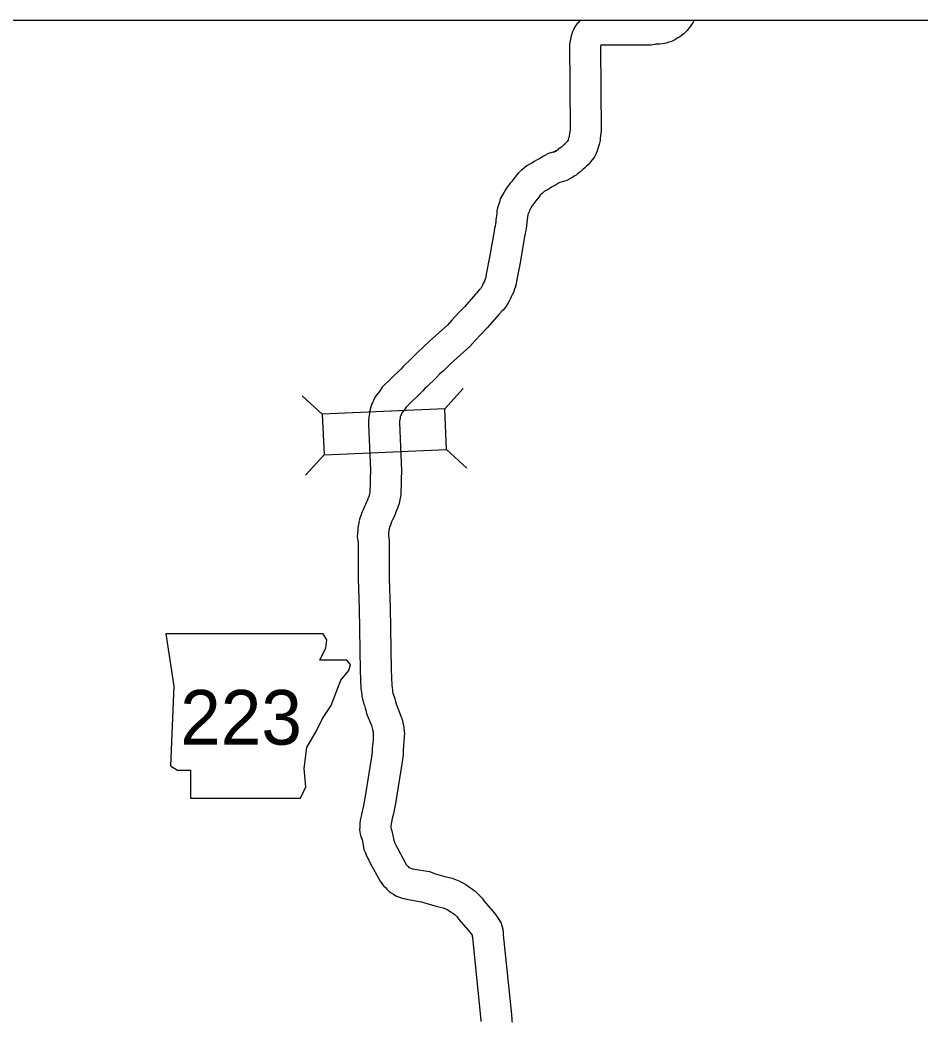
# Model space of a CAD drawing. Extents: x 1377389 to 1380723, y 1168351 to 1170484.
# Drawn here: x 1377955.3 to 1378042.4, y 1170291.8 to 1170388.8 of the extents above; entities that cross this region are included whole.
import ezdxf

# ---------------------------------------------------------------- set-up
doc = ezdxf.new("R2010")
doc.units = 0
doc.layers.add('B_Fill', color=7, linetype='Continuous')
doc.layers.add('B_Text', color=7, linetype='Continuous')

msp = doc.modelspace()

# ---------------------------------------------------------------- linework, layer by layer
at = {"layer": 'B_Fill'}
for p, q in [((1377996.362, 1170351.155), (1377998.146, 1170353.101)), ((1377984.494, 1170350.635), (1377982.547, 1170352.418)), ((1377996.536, 1170347.199), (1377998.482, 1170345.415)), ((1377984.667, 1170346.679), (1377982.884, 1170344.732))]:
    msp.add_line(p, q, dxfattribs=at)
for points in [[(1378009.472, 1170388.771), (1378009.248, 1170388.506), (1378009.182, 1170388.423), (1378008.939, 1170388.113), (1378008.81, 1170387.838), (1378008.716, 1170387.638), (1378008.644, 1170387.426), (1378008.552, 1170387.127), (1378008.547, 1170387.085), (1378008.48, 1170386.767), (1378008.426, 1170386.456), (1378008.501, 1170378.239), (1378008.486, 1170378.145), (1378008.414, 1170377.836), (1378008.377, 1170377.497), (1378008.377, 1170377.465), (1378008.341, 1170377.337), (1378008.311, 1170377.194), (1378008.293, 1170377.137), (1378008.198, 1170377.031), (1378008.039, 1170376.851), (1378007.989, 1170376.787), (1378007.926, 1170376.726), (1378007.859, 1170376.656), (1378007.744, 1170376.558), (1378007.648, 1170376.471), (1378007.338, 1170376.263), (1378007.261, 1170376.189), (1378007.147, 1170376.109), (1378006.876, 1170375.961)], [(1378020.475, 1170388.771), (1378020.38, 1170388.563), (1378020.119, 1170388.133), (1378019.805, 1170387.759), (1378019.503, 1170387.424), (1378019.089, 1170387.14), (1378018.857, 1170387.017), (1378018.67, 1170386.903), (1378018.286, 1170386.699), (1378018.023, 1170386.627), (1378017.777, 1170386.538), (1378017.38, 1170386.469), (1378017.151, 1170386.451), (1378017.032, 1170386.439), (1378016.79, 1170386.42), (1378016.685, 1170386.417), (1378016.674, 1170386.416), (1378016.31, 1170386.335), (1378011.508, 1170386.353), (1378011.468, 1170386.359), (1378011.443, 1170386.278), (1378011.428, 1170386.206), (1378011.504, 1170378.012), (1378011.431, 1170377.563), (1378011.381, 1170377.348), (1378011.386, 1170377.1), (1378011.282, 1170376.712), (1378011.256, 1170376.62), (1378011.214, 1170376.421), (1378011.111, 1170376.102), (1378011.021, 1170375.871), (1378010.856, 1170375.547), (1378010.612, 1170375.231), (1378010.443, 1170375.041), (1378010.349, 1170374.934), (1378010.224, 1170374.774), (1378010.053, 1170374.609), (1378009.924, 1170374.474), (1378009.726, 1170374.305), (1378009.405, 1170374.014), (1378009.216, 1170373.907), (1378009.074, 1170373.77), (1378008.865, 1170373.649), (1378008.732, 1170373.556), (1378008.17, 1170373.25)], [(1378007.172, 1170376.083), (1378006.39, 1170375.854), (1378005.894, 1170375.601), (1378005.547, 1170375.385), (1378005.241, 1170375.215), (1378004.992, 1170375.08), (1378004.764, 1170374.928), (1378004.594, 1170374.828), (1378004.3, 1170374.661), (1378004.063, 1170374.474), (1378003.764, 1170374.238), (1378003.501, 1170373.972), (1378003.298, 1170373.755), (1378003.094, 1170373.485), (1378002.969, 1170373.324), (1378002.834, 1170373.16), (1378002.68, 1170372.97), (1378002.534, 1170372.77), (1378002.372, 1170372.558), (1378002.18, 1170372.256), (1378002.106, 1170372.117), (1378001.947, 1170371.869), (1378001.712, 1170371.456), (1378001.642, 1170371.143), (1378001.604, 1170371.056), (1378001.442, 1170370.609), (1378001.401, 1170370.297), (1378001.378, 1170370.042), (1378001.35, 1170369.801), (1378001.33, 1170369.648), (1378001.296, 1170369.428), (1378001.283, 1170369.193), (1378001.266, 1170369.075), (1378001.217, 1170368.826), (1378001.181, 1170368.613), (1378001.132, 1170368.335), (1378000.696, 1170365.815), (1378000.373, 1170364.162), (1378000.336, 1170363.887), (1378000.255, 1170363.709), (1378000.201, 1170363.517), (1378000.195, 1170363.503), (1378000.082, 1170363.294), (1378000.008, 1170363.121), (1377999.94, 1170362.993), (1377999.882, 1170362.89), (1377999.8, 1170362.76), (1377999.767, 1170362.713), (1377999.699, 1170362.651), (1377999.547, 1170362.488), (1377999.422, 1170362.343), (1377999.339, 1170362.255), (1377999.131, 1170362.01), (1377998.265, 1170361.025), (1377997.727, 1170360.469), (1377997.023, 1170359.738), (1377996.614, 1170359.254), (1377994.914, 1170357.726), (1377994.197, 1170357.043), (1377993.764, 1170356.657), (1377993.387, 1170356.265), (1377993.139, 1170356.009), (1377992.876, 1170355.768), (1377992.599, 1170355.492), (1377992.326, 1170355.245), (1377992.091, 1170354.994), (1377990.3, 1170353.231), (1377990.027, 1170352.829), (1377989.821, 1170352.579), (1377989.652, 1170352.347), (1377989.497, 1170352.035), (1377989.464, 1170351.946), (1377989.432, 1170351.889), (1377989.361, 1170351.735), (1377989.277, 1170351.551), (1377989.12, 1170351.106), (1377989.064, 1170350.689), (1377989.006, 1170350.38), (1377988.971, 1170349.955), (1377988.981, 1170349.66), (1377989.178, 1170345.163), (1377989.135, 1170344.423), (1377989.135, 1170344.13), (1377989.123, 1170343.908), (1377989.119, 1170343.681), (1377989.11, 1170343.375), (1377989.104, 1170343.103), (1377989.065, 1170342.869), (1377989.047, 1170342.768), (1377989.004, 1170342.648), (1377988.906, 1170342.425), (1377988.839, 1170342.246), (1377988.787, 1170342.122), (1377988.693, 1170341.901), (1377988.586, 1170341.687), (1377988.448, 1170341.374), (1377988.338, 1170341.1), (1377988.25, 1170340.882), (1377988.145, 1170340.575), (1377988.085, 1170340.347)], [(1378008.17, 1170373.25), (1378007.504, 1170373.054), (1378007.37, 1170372.986), (1378007.069, 1170372.799), (1378006.686, 1170372.586), (1378006.542, 1170372.508), (1378006.358, 1170372.385), (1378006.095, 1170372.23), (1378005.976, 1170372.163), (1378005.921, 1170372.119), (1378005.77, 1170372), (1378005.664, 1170371.893), (1378005.597, 1170371.82), (1378005.474, 1170371.659), (1378005.311, 1170371.448), (1378005.157, 1170371.262), (1378005.061, 1170371.144), (1378004.938, 1170370.974), (1378004.831, 1170370.835), (1378004.776, 1170370.748), (1378004.699, 1170370.602), (1378004.539, 1170370.354), (1378004.507, 1170370.211), (1378004.395, 1170369.952), (1378004.377, 1170369.903), (1378004.362, 1170369.734), (1378004.327, 1170369.432), (1378004.299, 1170369.222), (1378004.284, 1170369.119), (1378004.271, 1170368.892), (1378004.223, 1170368.567), (1378004.169, 1170368.292), (1378004.138, 1170368.102), (1378004.086, 1170367.814), (1378003.646, 1170365.272), (1378003.335, 1170363.676), (1378003.279, 1170363.256), (1378003.174, 1170362.878), (1378003.08, 1170362.673), (1378003.026, 1170362.481), (1378002.883, 1170362.168), (1378002.787, 1170361.99), (1378002.713, 1170361.817), (1378002.573, 1170361.557), (1378002.461, 1170361.354), (1378002.296, 1170361.095), (1378002.041, 1170360.731), (1378001.817, 1170360.523), (1378001.776, 1170360.479), (1378001.65, 1170360.335), (1378001.578, 1170360.258), (1378001.401, 1170360.048), (1378000.47, 1170358.99), (1377999.885, 1170358.385), (1377999.252, 1170357.728), (1377998.774, 1170357.161), (1377996.952, 1170355.524), (1377996.231, 1170354.837), (1377995.846, 1170354.494), (1377995.545, 1170354.181), (1377995.231, 1170353.858), (1377994.949, 1170353.599), (1377994.664, 1170353.315), (1377994.431, 1170353.104), (1377994.24, 1170352.9), (1377992.616, 1170351.302), (1377992.43, 1170351.027), (1377992.234, 1170350.79), (1377992.192, 1170350.68), (1377992.11, 1170350.533), (1377992.088, 1170350.483), (1377992.06, 1170350.423), (1377992.052, 1170350.401), (1377992.027, 1170350.214), (1377991.983, 1170349.979), (1377991.975, 1170349.881), (1377991.979, 1170349.775), (1377992.182, 1170345.142), (1377992.135, 1170344.334), (1377992.135, 1170344.046), (1377992.122, 1170343.806), (1377992.119, 1170343.612), (1377992.109, 1170343.296), (1377992.099, 1170342.825), (1377992.021, 1170342.353), (1377991.954, 1170341.991), (1377991.795, 1170341.543), (1377991.688, 1170341.297), (1377991.626, 1170341.131), (1377991.548, 1170340.95), (1377991.418, 1170340.642), (1377991.301, 1170340.408), (1377991.214, 1170340.212), (1377991.121, 1170339.978), (1377991.061, 1170339.83), (1377991.02, 1170339.711), (1377990.99, 1170339.596)], [(1377988.076, 1170340.31), (1377987.99, 1170339.937), (1377987.954, 1170339.667), (1377987.927, 1170339.415), (1377987.904, 1170339.125), (1377987.872, 1170338.747), (1377987.951, 1170338.354), (1377987.96, 1170338.278), (1377987.98, 1170334.677), (1377988.074, 1170331.826), (1377988.161, 1170325.814), (1377988.239, 1170324.094), (1377988.288, 1170323.725), (1377988.315, 1170323.528), (1377988.341, 1170323.348), (1377988.383, 1170323.049), (1377988.478, 1170322.73), (1377988.534, 1170322.559), (1377988.572, 1170322.433), (1377988.647, 1170322.179), (1377988.714, 1170321.982), (1377988.793, 1170321.668), (1377989.258, 1170320.495), (1377989.336, 1170320.248), (1377989.361, 1170320.113), (1377989.411, 1170319.892), (1377989.428, 1170319.805), (1377989.435, 1170319.731), (1377989.442, 1170319.646), (1377989.441, 1170319.617), (1377989.437, 1170319.476), (1377989.418, 1170319.275), (1377989.41, 1170319.16), (1377989.382, 1170318.801), (1377989.344, 1170318.273), (1377989.339, 1170317.937), (1377989.256, 1170317.456), (1377988.628, 1170313.477), (1377988.494, 1170312.77), (1377988.419, 1170312.461), (1377988.349, 1170312.201), (1377988.253, 1170311.725), (1377988.179, 1170311.346), (1377988.124, 1170311.013), (1377988.119, 1170310.698), (1377988.112, 1170310.409), (1377988.167, 1170310.023), (1377988.245, 1170309.719), (1377988.325, 1170309.549), (1377988.34, 1170309.499), (1377988.345, 1170309.487), (1377988.534, 1170308.497), (1377988.671, 1170308.185), (1377988.748, 1170307.977), (1377988.9, 1170307.629), (1377989.011, 1170307.458), (1377989.115, 1170307.242), (1377990.102, 1170305.429), (1377990.429, 1170304.996), (1377990.574, 1170304.849), (1377990.734, 1170304.646), (1377990.972, 1170304.447), (1377991.168, 1170304.298), (1377991.384, 1170304.164), (1377991.617, 1170304.019), (1377991.87, 1170303.931), (1377991.981, 1170303.886), (1377992.238, 1170303.804), (1377992.427, 1170303.753), (1377992.647, 1170303.702), (1377994.117, 1170303.447), (1377994.535, 1170303.3), (1377995.608, 1170302.988), (1377996.195, 1170302.855), (1377996.498, 1170302.735), (1377996.531, 1170302.719), (1377996.647, 1170302.647), (1377996.795, 1170302.563), (1377996.918, 1170302.477), (1377997.127, 1170302.339), (1377997.229, 1170302.276), (1377997.264, 1170302.249), (1377997.35, 1170302.175), (1377997.428, 1170302.108), (1377997.513, 1170302.024), (1377997.562, 1170301.968), (1377997.715, 1170301.731), (1377998.657, 1170300.644), (1377998.895, 1170300.342), (1377999.006, 1170300.199), (1377999.017, 1170300.1), (1377999.032, 1170299.941), (1377999.82, 1170292.313), (1377999.831, 1170291.965), (1377999.835, 1170291.845)], [(1377990.999, 1170339.633), (1377990.945, 1170339.399), (1377990.933, 1170339.306), (1377990.914, 1170339.136), (1377990.897, 1170338.92), (1377990.914, 1170338.834), (1377990.959, 1170338.471), (1377990.98, 1170334.734), (1377991.073, 1170331.897), (1377991.16, 1170325.903), (1377991.23, 1170324.36), (1377991.261, 1170324.129), (1377991.286, 1170323.948), (1377991.312, 1170323.768), (1377991.323, 1170323.688), (1377991.34, 1170323.629), (1377991.395, 1170323.463), (1377991.447, 1170323.292), (1377991.507, 1170323.089), (1377991.595, 1170322.829), (1377991.655, 1170322.587), (1377992.085, 1170321.503), (1377992.253, 1170320.976), (1377992.301, 1170320.713), (1377992.346, 1170320.516), (1377992.4, 1170320.244), (1377992.424, 1170319.998), (1377992.45, 1170319.684), (1377992.439, 1170319.491), (1377992.433, 1170319.292), (1377992.408, 1170319.03), (1377992.402, 1170318.944), (1377992.374, 1170318.579), (1377992.343, 1170318.142), (1377992.335, 1170317.656), (1377992.216, 1170316.967), (1377991.584, 1170312.964), (1377991.428, 1170312.137), (1377991.326, 1170311.718), (1377991.271, 1170311.513), (1377991.195, 1170311.141), (1377991.132, 1170310.814), (1377991.12, 1170310.744), (1377991.119, 1170310.669), (1377991.183, 1170310.462), (1377991.244, 1170310.295), (1377991.417, 1170309.393), (1377991.454, 1170309.309), (1377991.531, 1170309.101), (1377991.552, 1170309.054), (1377991.631, 1170308.93), (1377991.785, 1170308.614), (1377992.631, 1170307.058), (1377992.703, 1170306.963), (1377992.827, 1170306.838), (1377992.887, 1170306.761), (1377992.913, 1170306.745), (1377992.999, 1170306.71), (1377993.085, 1170306.683), (1377993.16, 1170306.663), (1377993.243, 1170306.643), (1377994.875, 1170306.36), (1377995.451, 1170306.158), (1377996.36, 1170305.894), (1377997.085, 1170305.729), (1377997.715, 1170305.479), (1377997.988, 1170305.345), (1377998.179, 1170305.227), (1377998.399, 1170305.102), (1377998.603, 1170304.959), (1377998.743, 1170304.867), (1377998.947, 1170304.74), (1377999.159, 1170304.575), (1377999.3, 1170304.455), (1377999.469, 1170304.31), (1377999.695, 1170304.084), (1377999.958, 1170303.789), (1378000.121, 1170303.535), (1378000.971, 1170302.555), (1378001.255, 1170302.193), (1378001.489, 1170301.894), (1378001.601, 1170301.728), (1378001.813, 1170301.358), (1378001.846, 1170301.231), (1378001.982, 1170300.789), (1378001.992, 1170300.492), (1378002.002, 1170300.398), (1378002.017, 1170300.238), (1378002.815, 1170292.517), (1378002.83, 1170292.064), (1378002.834, 1170291.944)], [(1378002.829, 1170292.018), (1378002.842, 1170291.872), (1378002.871, 1170291.827), (1378002.899, 1170291.779)]]:
    msp.add_lwpolyline(points, dxfattribs=at)
for points in [[(1377996.362, 1170351.155), (1377984.494, 1170350.635), (1377984.667, 1170346.679), (1377996.536, 1170347.199)], [(1377969.375, 1170329.373), (1377970.137, 1170324.298), (1377969.798, 1170316.6), (1377970.475, 1170316.177), (1377971.744, 1170316.177), (1377971.744, 1170313.47), (1377982.402, 1170313.47), (1377982.91, 1170314.57), (1377982.741, 1170316.346), (1377982.994, 1170318.376), (1377983.925, 1170319.984), (1377984.517, 1170321.168), (1377985.363, 1170322.437), (1377985.87, 1170323.79), (1377986.293, 1170324.89), (1377987.055, 1170325.82), (1377987.224, 1170326.412), (1377986.885, 1170326.835), (1377984.263, 1170326.835), (1377984.855, 1170328.02), (1377984.94, 1170328.781), (1377984.589, 1170329.366)]]:
    msp.add_lwpolyline(points, close=True, dxfattribs=at)
at = {"layer": 'B_Text'}
msp.add_lwpolyline([(1377549.76, 1170388.771), (1378279.156, 1170388.771), (1378279.156, 1169604.285), (1377549.76, 1169604.285)], close=True, dxfattribs=at)

# ---------------------------------------------------------------- texts
at = {"layer": 'B_Fill'}
msp.add_text('223', height=5.28, dxfattribs=at).set_placement((1377970.749, 1170318.651))

doc.saveas('drawing.dxf')
